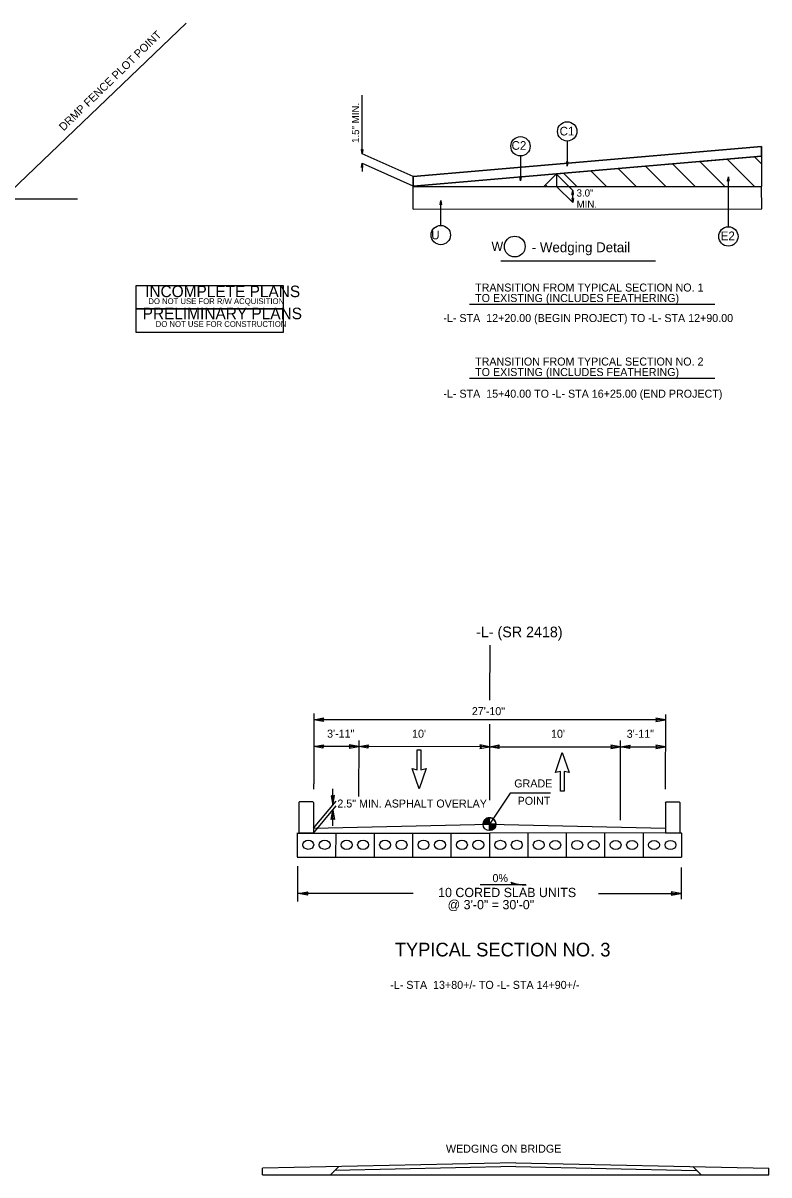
# Model space of a CAD drawing. Extents: x 1542177 to 1542464, y 45134 to 45344.
# Drawn here: x 1542361.9 to 1542417.8, y 45148.5 to 45234.8 of the extents above; entities that cross this region are included whole.
import ezdxf

# ---------------------------------------------------------------- set-up
doc = ezdxf.new("R2010")
doc.units = 0
for name, color, linetype in [('Default', 7, 'Continuous'), ('Old_Level_1', 7, 'Continuous'), ('Old_Level_2', 7, 'Continuous'), ('Old_Level_3', 7, 'Continuous'), ('Scratch_Level_3', 7, 'Continuous'), ('Typical Detail Wedge3 CELL', 7, 'Continuous'), ('Typical ID Circle CELL', 7, 'Continuous'), ('Typical Text General CELL', 7, 'Continuous'), ('Typical Text ID Circle CELL', 7, 'Continuous')]:
    doc.layers.add(name, color=color, linetype=linetype)

msp = doc.modelspace()

# ---------------------------------------------------------------- linework, layer by layer
at = {"layer": 'Default'}
for p, q in [((1542360.367, 45221.652), (1542374.107, 45234.847)), ((1542360.367, 45221.652), (1542365.968, 45221.652)), ((1542397.687, 45217.002), (1542409.276, 45217.008)), ((1542395.348, 45213.757), (1542413.728, 45213.757)), ((1542395.348, 45208.206), (1542413.728, 45208.206)), ((1542396.857, 45188.179), (1542396.855, 45184.073)), ((1542383.668, 45183.056), (1542383.665, 45177.786)), ((1542410.024, 45182.59), (1542383.668, 45182.601)), ((1542396.843, 45182.264), (1542396.841, 45176.573)), ((1542410.024, 45182.998), (1542410.021, 45177.39)), ((1542387.04, 45180.579), (1542383.666, 45180.581)), ((1542387.037, 45181.045), (1542387.035, 45176.829)), ((1542396.843, 45180.576), (1542387.038, 45180.581)), ((1542396.843, 45180.576), (1542406.649, 45180.571)), ((1542406.648, 45181.036), (1542406.644, 45175.07)), ((1542406.65, 45180.57), (1542409.55, 45180.569)), ((1542391.424, 45178.842), (1542391.424, 45180.334)), ((1542391.424, 45180.334), (1542391.704, 45180.334)), ((1542391.704, 45180.334), (1542391.704, 45178.842)), ((1542401.78, 45178.636), (1542402.3, 45180.144)), ((1542402.3, 45180.144), (1542402.82, 45178.636)), ((1542391.564, 45177.423), (1542391.044, 45178.931)), ((1542391.044, 45178.931), (1542391.424, 45178.842)), ((1542392.084, 45178.931), (1542391.564, 45177.423)), ((1542391.704, 45178.842), (1542392.084, 45178.931)), ((1542402.16, 45178.725), (1542401.78, 45178.636)), ((1542402.16, 45177.233), (1542402.16, 45178.725)), ((1542402.82, 45178.636), (1542402.44, 45178.725)), ((1542402.44, 45178.725), (1542402.44, 45177.233)), ((1542383.665, 45177.39), (1542383.665, 45177.786)), ((1542402.44, 45177.233), (1542402.16, 45177.233)), ((1542382.598, 45176.442), (1542382.55, 45176.394)), ((1542382.55, 45176.394), (1542382.55, 45174.101)), ((1542383.596, 45176.442), (1542382.598, 45176.442)), ((1542383.644, 45176.394), (1542383.596, 45176.442)), ((1542383.644, 45174.454), (1542385.355, 45176.482)), ((1542383.644, 45176.394), (1542383.644, 45174.101)), ((1542410.022, 45176.402), (1542410.07, 45176.449)), ((1542410.022, 45176.402), (1542410.022, 45174.108)), ((1542410.07, 45176.449), (1542411.068, 45176.449)), ((1542411.068, 45176.449), (1542411.115, 45176.402)), ((1542411.115, 45176.402), (1542411.115, 45174.108)), ((1542383.644, 45174.101), (1542385.355, 45176.129)), ((1542383.644, 45174.454), (1542396.833, 45174.765)), ((1542396.844, 45174.765), (1542396.363, 45174.765)), ((1542396.424, 45174.765), (1542396.367, 45174.824)), ((1542396.493, 45174.765), (1542396.378, 45174.881)), ((1542396.561, 45174.765), (1542396.394, 45174.933)), ((1542396.629, 45174.765), (1542396.414, 45174.98)), ((1542396.697, 45174.765), (1542396.438, 45175.024)), ((1542396.765, 45174.765), (1542396.467, 45175.064)), ((1542396.492, 45175.094), (1542396.492, 45175.094)), ((1542396.833, 45174.765), (1542396.499, 45175.1)), ((1542396.844, 45174.821), (1542396.535, 45175.132)), ((1542396.844, 45174.89), (1542396.573, 45175.163)), ((1542396.844, 45174.958), (1542396.614, 45175.188)), ((1542396.845, 45175.026), (1542396.662, 45175.21)), ((1542396.844, 45175.095), (1542396.711, 45175.228)), ((1542396.844, 45175.16), (1542396.767, 45175.24)), ((1542396.781, 45175.161), (1542396.844, 45175.095)), ((1542396.844, 45175.231), (1542396.828, 45175.247)), ((1542396.833, 45174.765), (1542410.022, 45174.454)), ((1542396.843, 45174.549), (1542397.058, 45174.335)), ((1542396.844, 45174.765), (1542396.844, 45175.247)), ((1542396.844, 45174.285), (1542396.844, 45174.765)), ((1542397.326, 45174.765), (1542396.844, 45174.765)), ((1542396.844, 45174.754), (1542397.179, 45174.42)), ((1542396.844, 45174.686), (1542397.142, 45174.388)), ((1542396.844, 45174.618), (1542397.102, 45174.358)), ((1542396.844, 45174.482), (1542397.011, 45174.314)), ((1542396.901, 45174.765), (1542397.213, 45174.456)), ((1542396.97, 45174.764), (1542397.24, 45174.493)), ((1542397.037, 45174.764), (1542397.266, 45174.536)), ((1542397.106, 45174.764), (1542397.289, 45174.583)), ((1542397.173, 45174.765), (1542397.307, 45174.632)), ((1542397.241, 45174.766), (1542397.319, 45174.688)), ((1542397.31, 45174.765), (1542397.326, 45174.75)), ((1542382.433, 45174.101), (1542396.872, 45174.1)), ((1542383.644, 45174.101), (1542382.559, 45174.101)), ((1542396.843, 45174.346), (1542396.902, 45174.287)), ((1542396.844, 45174.413), (1542396.959, 45174.297)), ((1542411.233, 45174.109), (1542396.872, 45174.1)), ((1542410.022, 45174.108), (1542411.106, 45174.108)), ((1542411.106, 45174.108), (1542411.185, 45174.108)), ((1542411.233, 45174.056), (1542411.185, 45174.108)), ((1542382.432, 45172.295), (1542411.232, 45172.297)), ((1542382.442, 45171.628), (1542382.442, 45168.955)), ((1542411.209, 45171.526), (1542411.209, 45169.148)), ((1542399.578, 45170.214), (1542396.154, 45170.211)), ((1542391.131, 45169.557), (1542382.494, 45169.557)), ((1542405.004, 45169.557), (1542411.174, 45169.557))]:
    msp.add_line(p, q, dxfattribs=at)
for points in [[(1542370.359, 45213.413), (1542370.359, 45215.176), (1542381.384, 45215.176), (1542381.384, 45213.413)], [(1542370.359, 45211.651), (1542370.359, 45213.413), (1542381.384, 45213.413), (1542381.384, 45211.651)], [(1542384.388, 45182.477), (1542383.668, 45182.601), (1542384.392, 45182.729), (1542384.3, 45182.601)], [(1542409.304, 45182.466), (1542410.024, 45182.59), (1542409.3, 45182.718), (1542409.392, 45182.59)], [(1542384.386, 45180.457), (1542383.666, 45180.581), (1542384.39, 45180.709), (1542384.298, 45180.581)], [(1542386.32, 45180.455), (1542387.04, 45180.579), (1542386.316, 45180.707), (1542386.408, 45180.579)], [(1542387.758, 45180.457), (1542387.038, 45180.581), (1542387.762, 45180.709), (1542387.67, 45180.581)], [(1542396.123, 45180.452), (1542396.843, 45180.576), (1542396.119, 45180.704), (1542396.211, 45180.576)], [(1542397.563, 45180.452), (1542396.843, 45180.576), (1542397.567, 45180.704), (1542397.475, 45180.576)], [(1542405.929, 45180.447), (1542406.649, 45180.571), (1542405.925, 45180.699), (1542406.017, 45180.571)], [(1542407.37, 45180.446), (1542406.65, 45180.57), (1542407.374, 45180.698), (1542407.282, 45180.57)], [(1542409.303, 45180.445), (1542410.023, 45180.569), (1542409.299, 45180.697), (1542409.391, 45180.569)], [(1542384.977, 45176.901), (1542385.101, 45176.181), (1542385.229, 45176.905), (1542385.101, 45176.813)], [(1542384.977, 45175.108), (1542385.101, 45175.828), (1542385.229, 45175.104), (1542385.101, 45175.196)], [(1542383.214, 45169.433), (1542382.494, 45169.557), (1542383.218, 45169.685), (1542383.126, 45169.557)], [(1542410.454, 45169.433), (1542411.174, 45169.557), (1542410.45, 45169.685), (1542410.542, 45169.557)]]:
    msp.add_lwpolyline(points, close=True, dxfattribs=at)
for points in [[(1542401.413, 45177.081), (1542398.397, 45177.083), (1542396.845, 45174.765)], [(1542398.523, 45170.216), (1542398.562, 45170.289), (1542398.547, 45170.346), (1542398.879, 45170.233), (1542399.161, 45170.21)]]:
    msp.add_lwpolyline(points, dxfattribs=at)
msp.add_circle((1542396.845, 45174.764), 0.481, dxfattribs=at)
for start, end in [(137.08657, 178.82696), (42.85927, 137.11053), (1.11887, 42.85927)]:
    msp.add_arc((1542396.845, 45174.764), 0.481, start, end, dxfattribs=at)
for centre in [(1542383.255, 45173.22), (1542384.489, 45173.22), (1542386.135, 45173.219), (1542387.369, 45173.218), (1542389.015, 45173.217), (1542390.249, 45173.217), (1542391.895, 45173.216), (1542393.129, 45173.215), (1542394.775, 45173.215), (1542396.009, 45173.214), (1542397.655, 45173.213), (1542398.889, 45173.213), (1542400.535, 45173.212), (1542401.769, 45173.211), (1542403.415, 45173.211), (1542404.649, 45173.21), (1542406.295, 45173.209), (1542407.529, 45173.209), (1542409.175, 45173.208), (1542410.409, 45173.207)]:
    msp.add_ellipse(centre, major_axis=(0.411, 0), ratio=0.833333, dxfattribs=at)
for centre, major_axis, start_param, end_param in [((1542399.637, 45174.482), (0.191, -4.268), 5.936482, 6.221152), ((1542398.411, 45170.3), (-0.005, 0.117), 3.805466, 5.820737)]:
    msp.add_ellipse(centre, major_axis=major_axis, ratio=0.938667, start_param=start_param, end_param=end_param, dxfattribs=at)
at = {"layer": 'Old_Level_1'}
for p, q in [((1542417.228, 45225.596), (1542391.112, 45223.33)), ((1542417.232, 45224.873), (1542417.228, 45225.596)), ((1542417.232, 45224.873), (1542391.117, 45222.608)), ((1542391.117, 45222.608), (1542417.232, 45224.873)), ((1542401.87, 45223.541), (1542417.232, 45224.873)), ((1542391.112, 45223.33), (1542391.117, 45222.608)), ((1542400.921, 45222.593), (1542401.87, 45223.541))]:
    msp.add_line(p, q, dxfattribs=at)
at = {"layer": 'Old_Level_2'}
for p, q in [((1542387.292, 45225.041), (1542387.292, 45229.432)), ((1542391.112, 45223.33), (1542387.292, 45225.041)), ((1542387.293, 45224.34), (1542387.293, 45223.723)), ((1542391.117, 45222.608), (1542387.329, 45224.304)), ((1542409.55, 45180.569), (1542410.023, 45180.569)), ((1542382.433, 45174.121), (1542382.431, 45172.321)), ((1542385.313, 45174.119), (1542385.311, 45172.319)), ((1542388.193, 45174.118), (1542388.191, 45172.318)), ((1542391.073, 45174.116), (1542391.071, 45172.316)), ((1542393.953, 45174.115), (1542393.951, 45172.315)), ((1542396.833, 45174.099), (1542396.831, 45172.314)), ((1542399.713, 45174.112), (1542399.711, 45172.312)), ((1542402.593, 45174.111), (1542402.591, 45172.311)), ((1542405.473, 45174.11), (1542405.471, 45172.31)), ((1542408.353, 45174.108), (1542408.351, 45172.308)), ((1542411.233, 45174.103), (1542411.231, 45172.303))]:
    msp.add_line(p, q, dxfattribs=at)
at = {"layer": 'Scratch_Level_3'}
for p, q in [((1542398.81, 45149.368), (1542379.833, 45148.97)), ((1542379.833, 45148.459), (1542379.833, 45148.97)), ((1542385.548, 45149.09), (1542384.917, 45148.459)), ((1542398.816, 45149.084), (1542385.258, 45148.799)), ((1542398.804, 45149.084), (1542412.363, 45148.799)), ((1542398.81, 45149.368), (1542417.788, 45148.97)), ((1542412.073, 45149.09), (1542412.704, 45148.459)), ((1542417.788, 45148.459), (1542417.788, 45148.97)), ((1542379.833, 45148.459), (1542417.788, 45148.459))]:
    msp.add_line(p, q, dxfattribs=at)
at = {"layer": 'Typical Detail Wedge3 CELL'}
for p, q in [((1542391.112, 45223.33), (1542417.228, 45225.596)), ((1542417.228, 45225.596), (1542417.232, 45224.873)), ((1542412.647, 45224.453), (1542417.232, 45224.873)), ((1542414.666, 45224.638), (1542416.711, 45222.595)), ((1542416.701, 45224.825), (1542417.234, 45224.291)), ((1542417.232, 45224.873), (1542417.242, 45222.595)), ((1542404.44, 45223.764), (1542405.593, 45222.612)), ((1542406.483, 45223.941), (1542407.837, 45222.587)), ((1542408.526, 45224.119), (1542410.052, 45222.593)), ((1542410.57, 45224.295), (1542412.27, 45222.595)), ((1542412.612, 45224.473), (1542414.49, 45222.595)), ((1542391.117, 45222.608), (1542391.112, 45223.33)), ((1542401.87, 45223.541), (1542401.87, 45222.594)), ((1542401.896, 45223.486), (1542403.117, 45222.266)), ((1542402.396, 45223.587), (1542403.392, 45222.591)), ((1542391.116, 45222.594), (1542417.242, 45222.595)), ((1542391.13, 45220.901), (1542391.116, 45222.594)), ((1542401.047, 45222.715), (1542401.165, 45222.597)), ((1542401.87, 45222.594), (1542403.084, 45221.38)), ((1542403.084, 45221.38), (1542403.082, 45222.3)), ((1542417.252, 45220.903), (1542417.242, 45222.595)), ((1542391.13, 45220.901), (1542417.252, 45220.903))]:
    msp.add_line(p, q, dxfattribs=at)
for points in [[(1542387.349, 45225.362), (1542387.292, 45225.32), (1542387.235, 45225.362), (1542387.292, 45225.041), (1542387.251, 45225.35), (1542387.267, 45225.338), (1542387.292, 45225.041), (1542387.283, 45225.326), (1542387.292, 45225.32), (1542387.292, 45225.041), (1542387.308, 45225.332), (1542387.324, 45225.344), (1542387.292, 45225.041), (1542387.34, 45225.356), (1542387.349, 45225.362), (1542387.292, 45225.041)], [(1542387.238, 45224.018), (1542387.293, 45224.06), (1542387.351, 45224.018), (1542387.293, 45224.34), (1542387.335, 45224.03), (1542387.319, 45224.041), (1542387.293, 45224.34), (1542387.302, 45224.054), (1542387.293, 45224.06), (1542387.293, 45224.34), (1542387.278, 45224.048), (1542387.262, 45224.036), (1542387.293, 45224.34), (1542387.245, 45224.024), (1542387.238, 45224.018), (1542387.293, 45224.34)], [(1542402.725, 45224.446), (1542402.668, 45224.404), (1542402.611, 45224.446), (1542402.668, 45224.124), (1542402.627, 45224.434), (1542402.643, 45224.421), (1542402.668, 45224.124), (1542402.659, 45224.41), (1542402.668, 45224.404), (1542402.668, 45224.124), (1542402.684, 45224.416), (1542402.7, 45224.428), (1542402.668, 45224.124), (1542402.717, 45224.44), (1542402.725, 45224.446), (1542402.668, 45224.124)], [(1542399.221, 45223.325), (1542399.165, 45223.283), (1542399.107, 45223.325), (1542399.165, 45223.004), (1542399.123, 45223.313), (1542399.14, 45223.3), (1542399.165, 45223.004), (1542399.156, 45223.289), (1542399.165, 45223.283), (1542399.165, 45223.004), (1542399.18, 45223.295), (1542399.197, 45223.307), (1542399.165, 45223.004), (1542399.213, 45223.319), (1542399.221, 45223.325), (1542399.165, 45223.004)], [(1542414.691, 45222.99), (1542414.748, 45223.032), (1542414.806, 45222.99), (1542414.748, 45223.311), (1542414.789, 45223.002), (1542414.773, 45223.014), (1542414.748, 45223.311), (1542414.757, 45223.026), (1542414.748, 45223.032), (1542414.748, 45223.311), (1542414.733, 45223.02), (1542414.716, 45223.008), (1542414.748, 45223.311), (1542414.7, 45222.996), (1542414.691, 45222.99), (1542414.748, 45223.311)], [(1542403.026, 45221.979), (1542403.082, 45222.021), (1542403.14, 45221.979), (1542403.082, 45222.301), (1542403.123, 45221.991), (1542403.107, 45222.002), (1542403.082, 45222.301), (1542403.091, 45222.015), (1542403.082, 45222.021), (1542403.082, 45222.301), (1542403.067, 45222.009), (1542403.051, 45221.997), (1542403.082, 45222.301), (1542403.034, 45221.985), (1542403.026, 45221.979), (1542403.082, 45222.301)], [(1542393.135, 45221.225), (1542393.191, 45221.267), (1542393.249, 45221.225), (1542393.191, 45221.546), (1542393.233, 45221.237), (1542393.216, 45221.249), (1542393.191, 45221.546), (1542393.2, 45221.261), (1542393.191, 45221.267), (1542393.191, 45221.546), (1542393.176, 45221.255), (1542393.16, 45221.243), (1542393.191, 45221.546), (1542393.143, 45221.231), (1542393.135, 45221.225), (1542393.191, 45221.546)], [(1542403.14, 45221.701), (1542403.084, 45221.659), (1542403.026, 45221.701), (1542403.084, 45221.38), (1542403.042, 45221.689), (1542403.059, 45221.677), (1542403.084, 45221.38), (1542403.075, 45221.665), (1542403.084, 45221.659), (1542403.084, 45221.38), (1542403.099, 45221.671), (1542403.115, 45221.683), (1542403.084, 45221.38), (1542403.132, 45221.695), (1542403.14, 45221.701), (1542403.084, 45221.38)]]:
    msp.add_lwpolyline(points, dxfattribs=at)
at = {"layer": 'Typical ID Circle CELL'}
for p, q in [((1542402.668, 45225.998), (1542402.668, 45224.124)), ((1542399.165, 45224.877), (1542399.165, 45223.004)), ((1542414.748, 45219.569), (1542414.754, 45223.194)), ((1542393.191, 45219.673), (1542393.191, 45221.546)), ((1542385.101, 45176.181), (1542385.101, 45177.417)), ((1542385.101, 45174.65), (1542385.101, 45175.828))]:
    msp.add_line(p, q, dxfattribs=at)
for centre, radius in [((1542402.668, 45226.723), 0.725), ((1542399.165, 45225.602), 0.725), ((1542393.191, 45218.948), 0.725), ((1542414.748, 45218.844), 0.725), ((1542398.738, 45218.086), 0.778)]:
    msp.add_circle(centre, radius, dxfattribs=at)

# ---------------------------------------------------------------- texts
at = {"layer": 'Default'}
for s, height, rotation, p in [('DRMP FENCE PLOT POINT', 0.6, 44.21518, (1542364.926, 45226.718)), ('-L- (SR 2418)', 0.8, 359.9469, (1542395.839, 45188.786)), ('27\'-10"', 0.6, 359.97292, (1542395.519, 45182.942)), ('3\'-11"', 0.6, 359.97292, (1542384.669, 45181.255)), ("10'", 0.6, 359.97292, (1542391.039, 45181.251)), ("10'", 0.6, 359.97292, (1542401.454, 45181.246)), ('3\'-11"', 0.6, 359.97292, (1542407.127, 45181.244)), ('GRADE', 0.6, 359.97292, (1542398.698, 45177.522)), ('2.5" MIN. ASPHALT OVERLAY', 0.6, 359.97292, (1542385.439, 45176.014)), ('POINT', 0.6, 359.97292, (1542398.952, 45176.221)), ('0%', 0.6, 0.01844, (1542397.068, 45170.423))]:
    msp.add_text(s, height=height, rotation=rotation, dxfattribs=at).set_placement(p)
for s, height, p in [('INCOMPLETE PLANS', 0.864, (1542371.03, 45214.291)), ('TRANSITION FROM TYPICAL SECTION NO. 1', 0.6, (1542395.765, 45214.711)), ('DO NOT USE FOR R/W ACQUISITION', 0.432, (1542371.274, 45213.77)), ('TO EXISTING (INCLUDES FEATHERING)', 0.6, (1542395.765, 45213.925)), ('PRELIMINARY PLANS', 0.864, (1542370.846, 45212.637)), ('DO NOT USE FOR CONSTRUCTION', 0.432, (1542371.829, 45212.06)), ('-L- STA  12+20.00 (BEGIN PROJECT) TO -L- STA 12+90.00', 0.6, (1542393.385, 45212.424)), ('TRANSITION FROM TYPICAL SECTION NO. 2', 0.6, (1542395.765, 45209.16)), ('TO EXISTING (INCLUDES FEATHERING)', 0.6, (1542395.765, 45208.374)), ('-L- STA  15+40.00 TO -L- STA 16+25.00 (END PROJECT)', 0.6, (1542393.385, 45206.749)), ('10 CORED SLAB UNITS', 0.696, (1542392.993, 45169.296)), ('@ 3\'-0" = 30\'-0"', 0.696, (1542393.7, 45168.384)), ('-L- STA  13+80+/- TO -L- STA 14+90+/-', 0.6, (1542389.403, 45162.414)), ('WEDGING ON BRIDGE', 0.6, (1542393.579, 45150.128))]:
    msp.add_text(s, height=height, dxfattribs=at).set_placement(p)
at = {"layer": 'Old_Level_3'}
msp.add_text('TYPICAL SECTION NO. 3', height=1.02627, rotation=359.97292, dxfattribs=at).set_placement((1542389.742, 45164.85))
at = {"layer": 'Typical Detail Wedge3 CELL'}
msp.add_text('1.5" MIN.', height=0.5423, rotation=90, dxfattribs=at).set_placement((1542387.071, 45225.858))
for s, p in [('3.0"', (1542403.37, 45221.833)), ('MIN.', (1542403.37, 45220.991))]:
    msp.add_text(s, height=0.5423, dxfattribs=at).set_placement(p)
at = {"layer": 'Typical Text General CELL'}
msp.add_text(' - Wedging Detail', height=0.74597, dxfattribs=at).set_placement((1542399.733, 45217.657))
at = {"layer": 'Typical Text ID Circle CELL'}
for s, height, p in [('C1', 0.649, (1542402.095, 45226.417)), ('C2', 0.649, (1542398.495, 45225.342)), ('   W  ', 0.696, (1542396.214, 45217.758))]:
    msp.add_text(s, height=height, dxfattribs=at).set_placement(p)
for s, p in [(' U ', (1542392.233, 45218.625)), ('E2', (1542414.171, 45218.562))]:
    msp.add_text(s, height=0.649, rotation=360, dxfattribs=at).set_placement(p)

doc.saveas('drawing.dxf')
